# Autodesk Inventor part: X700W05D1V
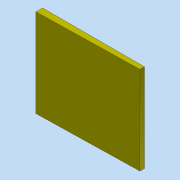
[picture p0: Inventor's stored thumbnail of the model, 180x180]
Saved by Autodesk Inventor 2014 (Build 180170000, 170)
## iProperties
Created: 2012-02
Part Number: X700W05D1V
Document SubType Name: Modeling
Designer: david.appleford
Density: 1 g/cm^3
Description: 1.5w EPS Wedge 1046mm - First Slope
Mass: 24729.7 g
Surface Area: 12625.4 cm^2
Volume: 24729.7 cm^3
Cost Center: £11.00
Material: Generic
Appearance: Stucco_01
Justset: False
Title: 1.5w EPS Wedge 1046mm - First Slope
Author: david.appleford
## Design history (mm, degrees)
sketch "Sketch1"
  geometry: L1 (1084.5, -59.5)-(1084.5, -94.5); L2 (1084.5, -94.5)-(277, -112); L3 (1084.5, -59.5)-(277, -59.5); L4 (277, -59.5)-(277, -112)
  constraints: 8 end point, 1 perpendicular
  dimensions: "d0" = 35 distance from line of L1.end L3; "d8" = 807.5 distance between parallel lines of L1 L4; "d16" = 52.5 distance from line of L2.end L3
extrude "Extrusion1" new body sketch "Sketch1" distance "d4" = 700; taper "d5" = 0 deg
body "Solid1"
